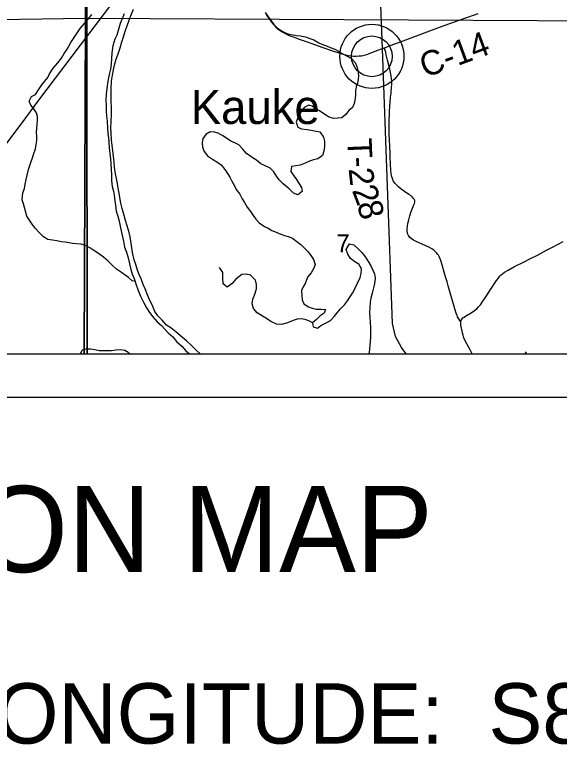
# Model space of a CAD drawing. Extents: x 0 to 34, y 0 to 22.
# Drawn here: x 5.477 to 6.742, y 13.194 to 14.887 of the extents above; entities that cross this region are included whole.
import ezdxf

# ---------------------------------------------------------------- set-up
doc = ezdxf.new("R2010")
doc.units = 0
for name, color, linetype in [('Default', 7, 'Continuous'), ('GM_X_County_Road', 7, 'Continuous'), ('GM_X_County_Road_Text', 7, 'Continuous'), ('GM_X_Major_River', 7, 'Continuous'), ('GM_X_Minor_River', 7, 'Continuous'), ('GM_X_Rail_Line', 7, 'Continuous'), ('GM_X_Section', 7, 'Continuous'), ('GM_X_Section_Text', 7, 'Continuous'), ('GM_X_State_Route', 7, 'Continuous'), ('GM_X_Township_Road', 7, 'Continuous'), ('GM_X_Township_Road_Text', 7, 'Continuous'), ('GM_X_Unincorporated', 7, 'Continuous'), ('GM_X_Unincorporated_Location', 7, 'Continuous'), ('GM_X_Unincorporated_Text', 7, 'Continuous'), ('SH_Data', 7, 'Continuous'), ('SH_Text', 7, 'Continuous')]:
    doc.layers.add(name, color=color, linetype=linetype)

msp = doc.modelspace()

# ---------------------------------------------------------------- linework, layer by layer
at = {"layer": 'Default'}
for points in [[(4.6336, 14.1), (5.6382, 14.1), (5.6415, 14.8783), (4.6247, 14.8633)], [(5.6382, 14.1), (6.8542, 14.1), (6.8396, 14.3761), (6.8411, 14.8726), (5.6415, 14.8783)]]:
    msp.add_lwpolyline(points, close=True, dxfattribs=at)
at = {"layer": 'GM_X_County_Road'}
for points in [[(6.0608, 14.8876), (6.0677, 14.8773), (6.0733, 14.87), (6.0794, 14.863), (6.0838, 14.8586), (6.0884, 14.8546), (6.0932, 14.8508), (6.101, 14.8458), (6.1097, 14.8413), (6.1185, 14.8376), (6.1237, 14.8355), (6.1399, 14.8297), (6.1565, 14.8239), (6.1651, 14.8209), (6.1926, 14.811), (6.2104, 14.8051), (6.237, 14.7965), (6.2459, 14.794), (6.2519, 14.7926), (6.258, 14.7916), (6.2641, 14.7911), (6.2703, 14.791), (6.2764, 14.7914), (6.2825, 14.7921), (6.2885, 14.7933), (6.2945, 14.7949), (6.3067, 14.7993), (6.3202, 14.8046), (6.3287, 14.8077), (6.3321, 14.809), (6.3354, 14.8103)], [(6.3354, 14.8103), (6.338, 14.8113), (6.3493, 14.8155), (6.3728, 14.824), (6.4658, 14.8589), (6.5065, 14.8739), (6.5446, 14.8872), (6.5533, 14.8903)], [(6.5129, 14.1745), (6.5134, 14.1767), (6.5143, 14.1791), (6.516, 14.1816), (6.5176, 14.1834), (6.5189, 14.1845), (6.5207, 14.1857), (6.5241, 14.1877), (6.5281, 14.19), (6.5373, 14.1956), (6.5449, 14.2009), (6.5498, 14.2047), (6.5543, 14.209), (6.5584, 14.2136), (6.5627, 14.2198), (6.5693, 14.2298), (6.5756, 14.2393), (6.5822, 14.2499), (6.5854, 14.2552), (6.5893, 14.2614), (6.594, 14.2677), (6.5957, 14.2702), (6.5994, 14.2752), (6.6014, 14.2775), (6.6038, 14.2808), (6.6069, 14.2838), (6.6105, 14.2869), (6.6147, 14.2899), (6.6228, 14.2946), (6.6379, 14.3029), (6.66, 14.3136), (6.6749, 14.3212), (6.6912, 14.3295), (6.71, 14.3401), (6.7273, 14.3488), (6.7509, 14.361)], [(6.5396, 14.1), (6.5347, 14.1095), (6.527, 14.1236), (6.5226, 14.1318), (6.5202, 14.1374), (6.5182, 14.1433), (6.5166, 14.1493), (6.513, 14.1675), (6.5127, 14.1706), (6.5127, 14.1737), (6.5129, 14.1745)]]:
    msp.add_lwpolyline(points, dxfattribs=at)
at = {"layer": 'GM_X_Major_River'}
for points in [[(5.7315, 14.8892), (5.7267, 14.8774), (5.7222, 14.8668), (5.7177, 14.8505), (5.714, 14.8398), (5.7095, 14.8303), (5.7047, 14.8147), (5.7025, 14.7984), (5.7022, 14.7855), (5.7015, 14.7722), (5.6996, 14.7612), (5.6967, 14.7483), (5.6937, 14.7331), (5.6911, 14.716), (5.6893, 14.7027), (5.689, 14.6886), (5.6894, 14.6765), (5.6899, 14.6636), (5.6907, 14.6526), (5.6915, 14.6401), (5.6927, 14.6245), (5.6935, 14.6112), (5.6951, 14.6014), (5.6959, 14.5915), (5.6963, 14.5786), (5.6979, 14.5653), (5.6999, 14.5517), (5.7007, 14.5422), (5.7015, 14.527), (5.7016, 14.5156), (5.702, 14.5027), (5.7036, 14.4887), (5.7063, 14.4777), (5.7082, 14.4682), (5.7098, 14.4553), (5.711, 14.4451), (5.7129, 14.4314), (5.7168, 14.4197), (5.7198, 14.4079), (5.7222, 14.3962), (5.7253, 14.3818), (5.7276, 14.3715), (5.7295, 14.3617), (5.7322, 14.348), (5.7368, 14.3363), (5.7403, 14.323), (5.7434, 14.309), (5.7472, 14.2961), (5.7499, 14.2859), (5.7553, 14.273), (5.7591, 14.2605), (5.7633, 14.2495), (5.7691, 14.234), (5.7767, 14.2188), (5.7832, 14.2071), (5.7905, 14.1961), (5.7977, 14.1863), (5.8083, 14.1746), (5.8182, 14.1659), (5.8334, 14.1492), (5.8441, 14.1398), (5.8532, 14.1292), (5.865, 14.1183), (5.8749, 14.1069), (5.883, 14.1)], [(5.9077, 14.1), (5.8991, 14.1082), (5.8873, 14.1199), (5.8763, 14.1301), (5.8668, 14.1384), (5.8516, 14.1516), (5.8398, 14.1607), (5.8299, 14.1671), (5.8197, 14.178), (5.8098, 14.1886), (5.8029, 14.1984), (5.7961, 14.2136), (5.7899, 14.2253), (5.7853, 14.2371), (5.7804, 14.2507), (5.7758, 14.2609), (5.7708, 14.2746), (5.7662, 14.2844), (5.7624, 14.2947), (5.7582, 14.3072), (5.7547, 14.3185), (5.7508, 14.3356), (5.7485, 14.3519), (5.7469, 14.3614), (5.745, 14.3716), (5.7427, 14.3818), (5.7381, 14.397), (5.7346, 14.4099), (5.7315, 14.4213), (5.7269, 14.4372), (5.7238, 14.4501), (5.7215, 14.463), (5.7199, 14.4728), (5.7176, 14.4846), (5.716, 14.4952), (5.7137, 14.5073), (5.711, 14.5183), (5.709, 14.5335), (5.7078, 14.5456), (5.7063, 14.5578), (5.7047, 14.5718), (5.7035, 14.5836), (5.7023, 14.5965), (5.7011, 14.6124), (5.7006, 14.6257), (5.701, 14.6375), (5.7016, 14.658), (5.7019, 14.672), (5.7011, 14.6857), (5.701, 14.7065), (5.7014, 14.716), (5.702, 14.7331), (5.7042, 14.7472), (5.7064, 14.7589), (5.7098, 14.7734), (5.7131, 14.7844), (5.7176, 14.7966), (5.7217, 14.8106), (5.7262, 14.8239), (5.7307, 14.8384), (5.7336, 14.849), (5.7385, 14.8616), (5.7433, 14.8749), (5.7478, 14.887), (5.7531, 14.9003)]]:
    msp.add_lwpolyline(points, dxfattribs=at)
at = {"layer": 'GM_X_Minor_River'}
msp.add_line((6.6626, 14.1), (6.6654, 14.1046), dxfattribs=at)
for points in [[(5.5972, 14.8047), (5.5989, 14.8075), (5.6079, 14.823), (5.614, 14.8322), (5.623, 14.8462), (5.6291, 14.8549), (5.6389, 14.8671), (5.6476, 14.8766), (5.6559, 14.8876)], [(6.0588, 14.8926), (6.0641, 14.8843), (6.0789, 14.8645), (6.0876, 14.8557), (6.0994, 14.8485), (6.1089, 14.8439), (6.1191, 14.8409), (6.1316, 14.8389), (6.1407, 14.8378), (6.152, 14.8355), (6.1626, 14.8317), (6.1714, 14.8286), (6.182, 14.8225), (6.1918, 14.8183), (6.2009, 14.8149), (6.2096, 14.8114), (6.2202, 14.8069), (6.2293, 14.8027), (6.2377, 14.797), (6.249, 14.7909), (6.2589, 14.7859), (6.2676, 14.7764), (6.2718, 14.7673), (6.2741, 14.7574), (6.2756, 14.7464), (6.2749, 14.7369), (6.273, 14.7285), (6.2703, 14.7201), (6.2681, 14.7106), (6.2681, 14.7019), (6.2677, 14.6924), (6.2651, 14.681), (6.2613, 14.6719), (6.253, 14.6647), (6.2462, 14.656), (6.2364, 14.6476), (6.2265, 14.6469), (6.2174, 14.6465), (6.2076, 14.6496), (6.197, 14.6553), (6.1852, 14.6644), (6.1765, 14.669), (6.1682, 14.6751), (6.1598, 14.677), (6.1489, 14.6717), (6.1432, 14.6633), (6.1383, 14.655), (6.1341, 14.6463), (6.1307, 14.6375), (6.1345, 14.6261), (6.1429, 14.6227), (6.1561, 14.6211), (6.1656, 14.6196), (6.1773, 14.6169), (6.1857, 14.6154), (6.194, 14.6032), (6.1963, 14.5937), (6.1963, 14.5816), (6.1952, 14.5705), (6.1922, 14.5603), (6.1808, 14.5527), (6.1706, 14.5501), (6.1615, 14.5474), (6.1517, 14.5425), (6.14, 14.5383), (6.1297, 14.5364), (6.1199, 14.5346), (6.1184, 14.5232), (6.1249, 14.5133)], [(5.6335, 14.3539), (5.6313, 14.3544), (5.6203, 14.3552), (5.6116, 14.356), (5.6033, 14.3575), (5.5946, 14.3591), (5.5851, 14.3602), (5.5753, 14.3625), (5.565, 14.364), (5.5544, 14.3656), (5.5438, 14.3721), (5.534, 14.3816), (5.5249, 14.3922), (5.5177, 14.401), (5.5112, 14.4101), (5.5055, 14.4196), (5.5021, 14.431), (5.5002, 14.4398), (5.4975, 14.4485), (5.4945, 14.4576), (5.4964, 14.474), (5.4997, 14.4842), (5.5016, 14.4937), (5.5039, 14.5048), (5.5061, 14.515), (5.5095, 14.5279), (5.5125, 14.5374), (5.5156, 14.5465), (5.5186, 14.5553), (5.5216, 14.5648), (5.5254, 14.5758), (5.5272, 14.586), (5.5284, 14.5955), (5.5283, 14.6047), (5.5276, 14.6142), (5.5283, 14.6237), (5.5294, 14.6328), (5.5302, 14.6419), (5.5302, 14.6506), (5.5279, 14.6598), (5.5218, 14.6689), (5.5146, 14.6776), (5.5104, 14.6864), (5.5161, 14.6974), (5.5252, 14.7023), (5.5342, 14.7152), (5.5403, 14.7243), (5.5471, 14.7331), (5.5539, 14.7418), (5.5577, 14.7502), (5.5667, 14.7631), (5.5773, 14.7756), (5.5856, 14.7866), (5.5924, 14.7968), (5.5972, 14.8047)], [(6.1249, 14.5133), (6.1317, 14.5049), (6.1374, 14.4946), (6.1427, 14.4859), (6.1446, 14.4768), (6.1348, 14.4692), (6.1245, 14.4734), (6.1143, 14.4833), (6.1007, 14.4951), (6.0915, 14.5038), (6.0851, 14.5126), (6.0786, 14.5225), (6.0707, 14.5312), (6.0574, 14.5369), (6.0487, 14.5415), (6.0389, 14.5495), (6.0305, 14.5545), (6.0157, 14.5651), (6.0066, 14.5754), (5.9975, 14.5849), (5.9881, 14.5902), (5.9793, 14.5941), (5.971, 14.5994), (5.9608, 14.6059), (5.9498, 14.6123), (5.9411, 14.6146), (5.9312, 14.6154), (5.9221, 14.6101), (5.9142, 14.6002), (5.9123, 14.59), (5.9135, 14.5801), (5.9173, 14.5698), (5.9252, 14.5599), (5.9366, 14.5523), (5.9465, 14.5459), (5.9567, 14.539), (5.9654, 14.5283), (5.9711, 14.5188), (5.9764, 14.5101), (5.9814, 14.5013), (5.9874, 14.4903), (5.9916, 14.4816), (5.9996, 14.4709), (6.0057, 14.4599), (6.0106, 14.4515), (6.017, 14.4405), (6.0246, 14.4302), (6.0307, 14.4214), (6.0368, 14.4131), (6.0451, 14.4039), (6.0569, 14.3956), (6.066, 14.3918), (6.0743, 14.3868), (6.0845, 14.3822), (6.0951, 14.378), (6.1039, 14.375), (6.1122, 14.3723), (6.1224, 14.3685), (6.1323, 14.3612), (6.1414, 14.3536), (6.1497, 14.3453), (6.1584, 14.3369), (6.1649, 14.3285), (6.1713, 14.319), (6.1751, 14.3072), (6.1721, 14.2989), (6.1657, 14.2882), (6.157, 14.278), (6.1525, 14.2651), (6.1468, 14.2556), (6.1434, 14.2472), (6.1438, 14.2351), (6.1446, 14.2259), (6.1484, 14.2161), (6.159, 14.2096), (6.1681, 14.2061), (6.1772, 14.2042), (6.1893, 14.2038), (6.1988, 14.203), (6.1954, 14.1943), (6.1863, 14.1886), (6.1776, 14.1799), (6.1685, 14.1723), (6.17, 14.1628), (6.1799, 14.1601), (6.1882, 14.1658), (6.2007, 14.1719), (6.2102, 14.1779), (6.2192, 14.1871), (6.226, 14.1954), (6.2336, 14.2049), (6.2427, 14.2136), (6.2502, 14.2231), (6.2555, 14.2315), (6.2616, 14.241), (6.2676, 14.2523), (6.2733, 14.2641), (6.2793, 14.277), (6.2819, 14.2869), (6.2827, 14.2972), (6.2762, 14.3086)], [(5.7568, 14.2682), (5.7503, 14.2699), (5.7416, 14.2775), (5.7333, 14.2828), (5.7249, 14.2886), (5.7136, 14.2965), (5.7037, 14.3061), (5.6939, 14.3152), (5.6832, 14.3243), (5.6719, 14.3327), (5.6632, 14.3388), (5.6514, 14.3461), (5.6416, 14.3518), (5.6335, 14.3539)], [(6.2762, 14.3086), (6.2668, 14.3139), (6.2565, 14.3215), (6.2505, 14.3314), (6.247, 14.3424), (6.2542, 14.3553), (6.2644, 14.3531), (6.2728, 14.3454), (6.2834, 14.3352), (6.2914, 14.3249), (6.2997, 14.312), (6.305, 14.3028), (6.3088, 14.2941), (6.3126, 14.2857), (6.3138, 14.2766), (6.313, 14.2679), (6.3119, 14.2595), (6.3096, 14.25), (6.307, 14.2409), (6.3044, 14.2291), (6.3025, 14.22), (6.3014, 14.2074), (6.301, 14.1953), (6.3014, 14.185), (6.3026, 14.1729), (6.3029, 14.1622), (6.3033, 14.1485), (6.3034, 14.1379), (6.3019, 14.1204), (6.3011, 14.1121), (6.3, 14.1029), (6.2997, 14.1)], [(6.1685, 14.1723), (6.1632, 14.1755), (6.1537, 14.1789), (6.1435, 14.1811), (6.1333, 14.1803), (6.1234, 14.1776), (6.1106, 14.1718), (6.0966, 14.1683), (6.0853, 14.1687), (6.072, 14.1754), (6.0621, 14.1826), (6.0523, 14.1879), (6.0401, 14.1954), (6.0318, 14.2052), (6.0287, 14.2162), (6.0298, 14.2268), (6.0343, 14.2364), (6.0384, 14.2508), (6.0387, 14.2614), (6.0364, 14.2709), (6.0246, 14.2826), (6.0144, 14.2852), (6.0045, 14.2844), (5.991, 14.2737), (5.9823, 14.2638), (5.9706, 14.2547), (5.9611, 14.263), (5.9603, 14.2762), (5.9606, 14.2891), (5.953, 14.3009)], [(5.7404, 14.1031), (5.7328, 14.1076), (5.7226, 14.1096), (5.712, 14.1084), (5.7021, 14.1069), (5.682, 14.107), (5.673, 14.1074), (5.6631, 14.1097), (5.6529, 14.1112), (5.6423, 14.1108), (5.6336, 14.1089), (5.6289, 14.1)], [(5.7445, 14.1), (5.7423, 14.1019), (5.7404, 14.1031)]]:
    msp.add_lwpolyline(points, dxfattribs=at)
at = {"layer": 'GM_X_Rail_Line'}
for points in [[(5.0891, 14.1), (5.1221, 14.1437), (5.272, 14.3429), (5.3972, 14.5075), (5.4919, 14.6329), (5.5336, 14.6891), (5.7438, 14.9674), (6.7216, 16.2626)], [(6.3861, 14.1), (6.3755, 14.1148), (6.3611, 14.1404), (6.3547, 14.1709), (6.3313, 14.8083), (6.3219, 15.0535), (6.3265, 15.1211), (6.3378, 15.1698), (6.3598, 15.2213), (6.4214, 15.3109), (6.7603, 15.7438), (7.1147, 16.1854), (7.1801, 16.2626)]]:
    msp.add_lwpolyline(points, dxfattribs=at)
at = {"layer": 'GM_X_Section'}
for points in [[(5.6379, 15.8781), (5.6415, 14.8783), (4.6247, 14.8633), (4.6171, 15.8766)], [(6.8272, 15.8734), (6.8411, 14.8726), (5.6415, 14.8783), (5.6379, 15.8781), (6.7969, 15.8732)]]:
    msp.add_lwpolyline(points, close=True, dxfattribs=at)
at = {"layer": 'GM_X_State_Route'}
msp.add_lwpolyline([(7.8042, 16.2626), (7.8024, 15.8725), (6.7968, 15.8774), (5.6416, 15.8841), (5.6436, 15.468), (5.6455, 14.1), (8.9, 14.1), (8.9, 18.8876), (8.7984, 18.8872), (8.8033, 17.8763), (8.296, 17.8766), (7.7904, 17.865), (7.8038, 16.9797), (7.9972, 16.9797), (7.9972, 16.2626)], close=True, dxfattribs=at)
msp.add_lwpolyline([(2.1, 14.1), (5.6455, 14.1), (5.6436, 15.468)], dxfattribs=at)
at = {"layer": 'GM_X_Township_Road'}
for points in [[(6.5129, 14.1745), (6.5106, 14.1776), (6.508, 14.1815), (6.5056, 14.1863), (6.5045, 14.1892), (6.5023, 14.1949), (6.4993, 14.2043), (6.496, 14.2151), (6.4879, 14.2414), (6.4834, 14.258), (6.4812, 14.2671), (6.4778, 14.279), (6.4673, 14.3144), (6.4652, 14.321), (6.4627, 14.3259), (6.461, 14.3289), (6.4592, 14.3316), (6.4571, 14.3341), (6.4552, 14.3364), (6.453, 14.3383), (6.4501, 14.341), (6.4459, 14.3437), (6.4402, 14.3471), (6.4314, 14.3512), (6.4081, 14.362), (6.4035, 14.3643), (6.3979, 14.3678), (6.3945, 14.3703), (6.3927, 14.3726), (6.3912, 14.3751), (6.39, 14.3778), (6.3889, 14.3808), (6.3882, 14.3836), (6.3881, 14.3868), (6.3882, 14.3902), (6.389, 14.3962), (6.39, 14.4024), (6.3919, 14.4115), (6.3945, 14.4205), (6.3976, 14.4302), (6.4006, 14.4381), (6.4039, 14.4457), (6.4054, 14.4492), (6.4064, 14.4525), (6.406, 14.4555), (6.4053, 14.4583), (6.4033, 14.461), (6.4006, 14.4638), (6.3975, 14.467), (6.3923, 14.4702), (6.3821, 14.4768), (6.3748, 14.4827), (6.3682, 14.4879), (6.3635, 14.4921), (6.3599, 14.4963), (6.3582, 14.4989), (6.3562, 14.5014), (6.355, 14.5044), (6.354, 14.5073), (6.3523, 14.5135), (6.3513, 14.5195), (6.3504, 14.5256), (6.3497, 14.5412), (6.3489, 14.5567), (6.3487, 14.566), (6.3482, 14.5816), (6.3476, 14.5971), (6.3468, 14.6094), (6.3465, 14.6215), (6.3465, 14.6374), (6.3475, 14.6623), (6.3483, 14.6746), (6.3489, 14.6838), (6.3499, 14.696), (6.3509, 14.7052), (6.3512, 14.7083), (6.3517, 14.7177), (6.3527, 14.7269), (6.3528, 14.7331), (6.3524, 14.7393), (6.3514, 14.7455), (6.3479, 14.7606), (6.3425, 14.7817), (6.3398, 14.7938), (6.3386, 14.7999), (6.3354, 14.8103)], [(6.5129, 14.1745), (6.5134, 14.1767), (6.5143, 14.1791), (6.516, 14.1816), (6.5176, 14.1834), (6.5189, 14.1845), (6.5207, 14.1857), (6.5241, 14.1877), (6.5281, 14.19), (6.5373, 14.1956), (6.5449, 14.2009), (6.5498, 14.2047), (6.5543, 14.209), (6.5584, 14.2136), (6.5627, 14.2198), (6.5693, 14.2298), (6.5756, 14.2393), (6.5822, 14.2499), (6.5854, 14.2552), (6.5893, 14.2614), (6.594, 14.2677), (6.5957, 14.2702), (6.5994, 14.2752), (6.6014, 14.2775), (6.6038, 14.2808), (6.6069, 14.2838), (6.6105, 14.2869), (6.6147, 14.2899), (6.6228, 14.2946), (6.6379, 14.3029), (6.66, 14.3136), (6.6749, 14.3212), (6.6912, 14.3295), (6.71, 14.3401), (6.7273, 14.3488), (6.7509, 14.361)], [(6.5396, 14.1), (6.5347, 14.1095), (6.527, 14.1236), (6.5226, 14.1318), (6.5202, 14.1374), (6.5182, 14.1433), (6.5166, 14.1493), (6.513, 14.1675), (6.5127, 14.1706), (6.5127, 14.1737), (6.5129, 14.1745)]]:
    msp.add_lwpolyline(points, dxfattribs=at)
at = {"layer": 'GM_X_Unincorporated'}
for radius in [0.0744, 0.0472]:
    msp.add_circle((6.3065, 14.7906), radius, dxfattribs=at)
at = {"layer": 'GM_X_Unincorporated_Location'}
msp.add_line((6.3065, 14.7906), (6.3065, 14.7906), dxfattribs=at)
at = {"layer": 'SH_Data'}
for p, q in [((2.1, 14.1), (8.9, 14.1)), ((2, 14), (9, 14))]:
    msp.add_line(p, q, dxfattribs=at)

# ---------------------------------------------------------------- texts
at = {"layer": 'GM_X_County_Road_Text'}
msp.add_text('C-14', height=0.05682, rotation=20.2756, dxfattribs=at).set_placement((6.4302, 14.7402))
at = {"layer": 'GM_X_Section_Text'}
msp.add_text('7', height=0.0419, rotation=0, dxfattribs=at).set_placement((6.2239, 14.3359))
at = {"layer": 'GM_X_Township_Road_Text'}
for s, rotation, p in [('T', 272.3256, (6.2491, 14.5997)), ('-', 272.9432, (6.2508, 14.5566)), ('2', 276.1212, (6.2523, 14.5298)), ('2', 290.7198, (6.2597, 14.4797)), ('8', 284.0773, (6.2716, 14.4486))]:
    msp.add_text(s, height=0.0568, rotation=rotation, dxfattribs=at).set_placement(p)
at = {"layer": 'GM_X_Unincorporated_Text'}
msp.add_text('Kauke', height=0.07898, rotation=0, dxfattribs=at).set_placement((5.886, 14.6336))
at = {"layer": 'SH_Text'}
for s, height, p in [('LOCATION MAP', 0.2, (4.4269, 13.5937)), ('LATITUDE:  N40°45\'21"     LONGITUDE:  S81°59\'48"', 0.14, (3.071, 13.1958))]:
    msp.add_text(s, height=height, dxfattribs=at).set_placement(p)

doc.saveas('drawing.dxf')
